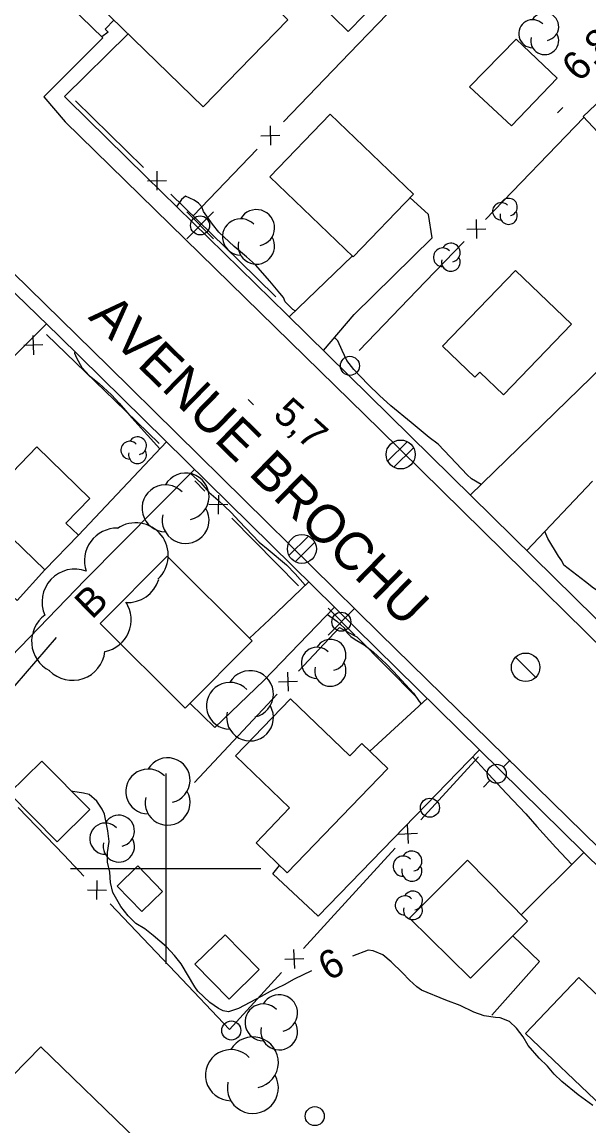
# Model space of a CAD drawing. Extents: x 381879 to 384696, y 5564785 to 5567594.
# Drawn here: x 382984.9 to 383044.4, y 5565173 to 5565288.9 of the extents above; entities that cross this region are included whole.
import ezdxf

# ---------------------------------------------------------------- set-up
doc = ezdxf.new("R2010")
doc.units = 0
for name, color, linetype in [('Niveau 19', 7, 'Continuous'), ('Niveau 2', 7, 'Continuous'), ('Niveau 21', 7, 'Continuous'), ('Niveau 22', 7, 'Continuous'), ('Niveau 3', 7, 'Continuous'), ('Niveau 31', 7, 'Continuous'), ('Niveau 36', 7, 'Continuous'), ('Niveau 37', 7, 'Continuous'), ('Niveau 44', 7, 'Continuous'), ('Niveau 52', 7, 'Continuous'), ('Niveau 61', 7, 'Continuous')]:
    doc.layers.add(name, color=color, linetype=linetype)

msp = doc.modelspace()

# ---------------------------------------------------------------- linework, layer by layer
at = {"layer": 'Niveau 19'}
for points in [[(383016.56, 5565254.4), (383019.78, 5565258.2), (383027.98, 5565266.25), (383027.6, 5565268.71), (383025.64, 5565270.47)], [(383019.61, 5565264.34), (383012.96, 5565257.94)], [(382977.69, 5565252.36), (382980.28, 5565250.02), (382987.48, 5565257.22)], [(383051.28, 5565248.2), (383045.95, 5565252.85), (383031.98, 5565239.23)], [(383000.09, 5565244.82), (382990.83, 5565235.01)], [(382987.32, 5565231.38), (382984.4, 5565228.17), (382978.03, 5565233.92), (382972.73, 5565228.26), (382967.87, 5565228.52), (382970.4, 5565224.82), (382975.08, 5565224.12), (382980.11, 5565223.76), (382983.75, 5565222.23), (382991.54, 5565230.32), (383003.03, 5565241.92)], [(383037.9, 5565233.41), (383044.81, 5565240.7)], [(383008.8, 5565224.2), (383010.89, 5565226.15), (383015.03, 5565230.11)], [(383017.72, 5565227.46), (383010.31, 5565219.74), (383005.16, 5565214.81), (383002.56, 5565217.35)], [(383021.42, 5565212.33), (383027.45, 5565217.88)], [(383032.94, 5565212.49), (383016.01, 5565195.01), (383011.25, 5565199.45), (383011.95, 5565200.34)], [(383043.9, 5565201.7), (383037.34, 5565195.17)], [(383036.43, 5565192.93), (383039.26, 5565190.26), (383034.24, 5565184.6)]]:
    msp.add_lwpolyline(points, dxfattribs=at)
at = {"layer": 'Niveau 2'}
for points in [[(383013.6, 5565258.56), (383013.34, 5565258.72), (383012.56, 5565259.52), (383012.38, 5565259.99), (383011.99, 5565260.43), (383010.95, 5565261.7), (383009.42, 5565263.41), (383008.48, 5565264.26), (383007.2, 5565265.35), (383005.58, 5565266.85), (383004.91, 5565267.68), (383003.96, 5565269.02), (383003.78, 5565269.51), (383003.45, 5565269.89), (383002.98, 5565270.21), (383002.07, 5565270.63), (383001.67, 5565270.27), (383001.37, 5565269.86), (383001.14, 5565269.53)], [(383033.13, 5565240.35), (383032.09, 5565240.94), (383031.64, 5565241.37), (383030.49, 5565242.57), (383028.59, 5565244.57), (383027.65, 5565245.29), (383025.76, 5565246.85), (383023.62, 5565248.6), (383022.43, 5565249.68), (383021.25, 5565250.85), (383019.74, 5565252.43), (383019.02, 5565253.36), (383018.53, 5565254.42), (383018.06, 5565255.41), (383017.73, 5565255.79)], [(382990.46, 5565254.3), (382990.44, 5565254.14), (382990.62, 5565253.65), (382991.2, 5565252.61), (382992, 5565251.74), (382993.01, 5565250.96), (382994.32, 5565249.76), (382995.1, 5565248.89), (382996.44, 5565247.33), (382998.1, 5565245.53), (382999.38, 5565244.07)], [(383002.62, 5565241.51), (383003.69, 5565240.5), (383004.52, 5565239.55), (383005.5, 5565238.69), (383006.87, 5565237.39), (383007.7, 5565236.49), (383009.82, 5565234.3), (383010.75, 5565233.51), (383012.68, 5565231.89), (383013.59, 5565230.97), (383014.66, 5565229.76)], [(383057.47, 5565222.55), (383056.98, 5565222.9), (383056.22, 5565223.69), (383055, 5565224.89), (383054.13, 5565225.49), (383053.25, 5565226.01), (383052.35, 5565226.69), (383051.33, 5565227.06), (383050.29, 5565227.3), (383047.99, 5565227.92), (383046.92, 5565228.33), (383045.92, 5565228.82), (383044.92, 5565229.45), (383044.08, 5565230.11), (383041.79, 5565231.86), (383041.58, 5565232.32), (383041.24, 5565232.81), (383040.11, 5565234.66), (383039.79, 5565235.41)], [(383016.99, 5565226.69), (383017.98, 5565225.99)], [(383017.98, 5565225.99), (383018.73, 5565225.27), (383019.05, 5565224.77), (383019.43, 5565224.38), (383019.9, 5565224.06), (383020.85, 5565223.51), (383021.78, 5565222.76), (383023.15, 5565221.52), (383023.91, 5565220.7), (383026, 5565218.43), (383026.6, 5565217.56), (383026.81, 5565217.29)], [(383032.21, 5565211.74), (383032.75, 5565211.17), (383033.89, 5565209.91), (383035.78, 5565207.89), (383037.8, 5565205.76), (383038.98, 5565204.43), (383040.96, 5565202.22), (383042.64, 5565200.44)], [(383015.31, 5565189.28), (383013.49, 5565188.38), (383012.45, 5565187.8), (383010.97, 5565187.1), (383010.04, 5565186.57), (383007.66, 5565185.31), (383006.58, 5565184.96), (383006.02, 5565185.05), (383005.55, 5565185.3), (383004.63, 5565185.95), (383003.36, 5565187.13), (383003.07, 5565187.6), (383001.62, 5565190), (383000.92, 5565190.88), (383000.07, 5565191.78), (382998.7, 5565192.99), (382997.82, 5565193.66), (382996.85, 5565194.25), (382996.06, 5565195.05), (382995.3, 5565196.01), (382994.45, 5565197.49), (382994.2, 5565198.54), (382994.14, 5565199.62), (382993.9, 5565200.69), (382993.89, 5565201.71), (382994.05, 5565202.84), (382993.91, 5565203.97), (382993.57, 5565205.73), (382993.32, 5565206.23), (382992.78, 5565207.1), (382991.95, 5565207.79), (382991.38, 5565207.93), (382990.26, 5565208.11), (382990.1, 5565208.14)], [(383044.84, 5565175.13), (383043.29, 5565176.24), (383041.58, 5565177.63), (383040.78, 5565178.42), (383040.07, 5565179.26), (383039.21, 5565180.09), (383038.05, 5565181.42), (383037.52, 5565182.32), (383036.84, 5565183.23), (383036.08, 5565183.93), (383035.12, 5565184.34), (383034.61, 5565184.35), (383033.44, 5565184.54), (383032.36, 5565184.94), (383030.92, 5565185.61), (383029.41, 5565186.18), (383026.86, 5565187.25), (383026.37, 5565187.6), (383025.59, 5565188.27), (383024.86, 5565189.05), (383023.67, 5565190.22), (383022.8, 5565190.94), (383021.77, 5565191.38), (383021.24, 5565191.42), (383019.61, 5565190.82)]]:
    msp.add_lwpolyline(points, dxfattribs=at)
at = {"layer": 'Niveau 21'}
msp.add_lwpolyline([(382987.2, 5565281.06), (382989.44, 5565278.42), (383022.49, 5565246.1), (383059.26, 5565209.91), (383088.37, 5565181.5), (383101.7, 5565168.8)], dxfattribs=at)
at = {"layer": 'Niveau 22'}
for points in [[(382994.58, 5565289.12), (382993.64, 5565288.16), (382993.96, 5565287.85), (382993.31, 5565287.34)], [(382989.72, 5565280.74), (382989.39, 5565281.09), (382996.07, 5565287.68)], [(382989.72, 5565280.74), (382997.91, 5565272.69), (383012.71, 5565258.19), (383105.48, 5565166.92), (383105.5, 5565166.9)], [(382963, 5565271.7), (382966.05, 5565274.15), (382968.58, 5565274.75), (382971.52, 5565274.09), (382973.8, 5565272.5), (382994.02, 5565252.72), (383022.46, 5565224.72), (383053.73, 5565194.11), (383080.99, 5565167.59), (383084.55, 5565163.99)], [(383092.98, 5565153.68), (383056.83, 5565188.98), (383017.75, 5565227.43), (382988.78, 5565255.96), (382969.58, 5565274.53)]]:
    msp.add_lwpolyline(points, dxfattribs=at)
at = {"layer": 'Niveau 3'}
for p, q in [((383041.12, 5565279.36), (383041.69, 5565279.93)), ((383008.66, 5565249.26), (383009.23, 5565248.69))]:
    msp.add_line(p, q, dxfattribs=at)
at = {"layer": 'Niveau 31'}
for points in [[(383003.94, 5565280.01), (382986.87, 5565296.63), (382988.63, 5565298.43), (382984.43, 5565302.53), (382982.52, 5565300.57), (382962.24, 5565320.32), (382969.15, 5565327.42), (382972.16, 5565324.49), (382979.7, 5565332.23), (382986.68, 5565325.44), (382979.09, 5565317.64), (382989.54, 5565307.45), (382987.76, 5565305.63), (382988.83, 5565304.59), (382987.51, 5565303.24), (382990.5, 5565300.32), (382995.79, 5565305.75), (383012.84, 5565289.15)], [(383015.99, 5565290.99), (383019.45, 5565294.53), (383022.6, 5565291.46), (383019.14, 5565287.92)], [(383036.3, 5565278), (383041.1, 5565283), (383036.8, 5565287.1), (383031.9, 5565282.1)], [(383043.82, 5565278.99), (383046.43, 5565281.44), (383048.96, 5565278.74), (383046.35, 5565276.29)], [(383017.25, 5565279.22), (383026, 5565270.84), (383019.69, 5565264.26), (383010.94, 5565272.64)], [(383042.6, 5565257.19), (383035.45, 5565249.76), (383032.97, 5565252.15), (383032.45, 5565251.61), (383029.06, 5565254.87), (383036.73, 5565262.83)], [(382987.32, 5565231.38), (382980.42, 5565238.03), (382986.46, 5565244.28), (382992.05, 5565238.88), (382989.53, 5565236.27), (382990.83, 5565235.01)], [(383000.14, 5565232.81), (383009.09, 5565223.92), (383002.06, 5565216.85), (382993.11, 5565225.74)], [(383023.31, 5565210.51), (383012.76, 5565199.56), (383009.49, 5565202.72), (383013, 5565206.37), (383007.33, 5565211.83), (383013.11, 5565217.83), (383019.33, 5565211.84), (383020.59, 5565213.13)], [(382986.99, 5565211.3), (382992.02, 5565206.2), (382988.59, 5565202.81), (382983.56, 5565207.91)], [(382997.06, 5565200.28), (382999.66, 5565197.61), (382997.5, 5565195.5), (382994.9, 5565198.17)], [(383032, 5565188.5), (383038, 5565194.5), (383031.7, 5565200.9), (383025.6, 5565194.8)], [(383006.23, 5565193.06), (383009.82, 5565189.39), (383006.65, 5565186.29), (383003.06, 5565189.96)], [(383043.37, 5565188.55), (383051.38, 5565180.93), (383045.79, 5565175.06), (383037.78, 5565182.68)], [(382986.9, 5565181.3), (382980.9, 5565175.2), (382991, 5565165.3), (382997, 5565171.5)]]:
    msp.add_lwpolyline(points, close=True, dxfattribs=at)
at = {"layer": 'Niveau 36'}
for p, q in [((383005.03, 5565268.96), (383002.21, 5565266.14)), ((383005.03, 5565266.14), (383002.21, 5565268.96)), ((383025.36, 5565244.83), (383023.3, 5565242.79)), ((383023.96, 5565242.15), (383026.02, 5565244.19)), ((383014.99, 5565234.91), (383012.93, 5565232.87)), ((383013.59, 5565232.23), (383015.65, 5565234.27)), ((383019.86, 5565227.34), (383017.04, 5565224.52)), ((383019.86, 5565224.52), (383017.04, 5565227.34)), ((383038.86, 5565220.08), (383036.74, 5565222.2)), ((383036.17, 5565211.38), (383035.46, 5565210.68)), ((383033.35, 5565208.55), (383034.04, 5565209.27))]:
    msp.add_line(p, q, dxfattribs=at)
for centre, radius in [((383003.61, 5565267.55), 1), ((383019.34, 5565252.8), 1), ((383024.67, 5565243.49), 1.52), ((383014.3, 5565233.57), 1.52), ((383018.44, 5565225.93), 1), ((383037.79, 5565221.14), 1.5), ((383034.75, 5565209.96), 1), ((383027.74, 5565206.4), 1), ((383006.89, 5565183), 1), ((383015.65, 5565174.01), 1)]:
    msp.add_circle(centre, radius, dxfattribs=at)
at = {"layer": 'Niveau 37'}
for p, q in [((383010.97, 5565277.99), (383011.01, 5565275.99)), ((383009.99, 5565276.97), (383011.99, 5565277.01)), ((382999.11, 5565271.24), (382999.09, 5565273.24)), ((382998.1, 5565272.23), (383000.1, 5565272.25)), ((383031.61, 5565267.14), (383033.61, 5565267.18)), ((383032.59, 5565268.16), (383032.63, 5565266.16)), ((382986.14, 5565253.96), (382986.07, 5565255.97)), ((382987.1, 5565255), (382985.1, 5565254.93)), ((383005.53, 5565239.23), (383005.52, 5565237.22)), ((383006.53, 5565238.22), (383004.52, 5565238.23)), ((383013.85, 5565219.65), (383011.84, 5565219.58)), ((383012.88, 5565218.62), (383012.81, 5565220.62)), ((383025.48, 5565202.63), (383025.39, 5565204.63)), ((383026.44, 5565203.68), (383024.44, 5565203.59)), ((382992.77, 5565196.75), (382992.82, 5565198.75)), ((382991.79, 5565197.78), (382993.79, 5565197.73)), ((383014.52, 5565190.54), (383012.52, 5565190.45)), ((383013.57, 5565189.5), (383013.47, 5565191.5))]:
    msp.add_line(p, q, dxfattribs=at)
for points in [[(383026.24, 5565292.84), (383019.31, 5565285.63)], [(383019.31, 5565285.63), (383012.38, 5565278.43)], [(382990.52, 5565280.63), (382997.67, 5565273.64)], [(383043.91, 5565278.89), (383033.57, 5565268.17)], [(383009.6, 5565275.54), (383002.87, 5565268.55)], [(383000.53, 5565270.84), (383007.68, 5565263.85)], [(383031.35, 5565265.86), (383027.25, 5565261.61)], [(383007.68, 5565263.85), (383011.58, 5565260.03)], [(383027.25, 5565261.61), (383020.31, 5565254.42)], [(382987.48, 5565256.1), (382994.66, 5565249.15)], [(382994.66, 5565249.15), (382999.33, 5565244.63)], [(383004.12, 5565239.65), (383003.05, 5565240.73)], [(383013.96, 5565229.69), (383006.93, 5565236.8)], [(382988.51, 5565224.26), (382981.97, 5565216.7)], [(383013.96, 5565220.73), (383018.24, 5565225.31), (383019.78, 5565224.49)], [(383019.78, 5565224.49), (383020.06, 5565224.34), (383026.31, 5565218.05)], [(383003.04, 5565209.05), (383011.71, 5565218.33)], [(383026.78, 5565205.11), (383032.84, 5565211.75)], [(382984.5, 5565206.42), (382989.33, 5565201.4), (382991.41, 5565199.2)], [(383017.35, 5565194.77), (383024.09, 5565202.16)], [(382994.17, 5565196.3), (383001.05, 5565189.05)], [(383014.46, 5565191.6), (383017.35, 5565194.77)], [(383001.05, 5565189.05), (383006.7, 5565183.1), (383012.15, 5565189.09)]]:
    msp.add_lwpolyline(points, dxfattribs=at)
at = {"layer": 'Niveau 44'}
for centre, radius, start, end in [((383038.53, 5565287.68), 1.47, 44.1153, 269.8039), ((383039.79, 5565288.42), 1.47, 282.2692, 149.7262), ((383039.79, 5565286.95), 1.47, 166.9368, 29.6212), ((383035.23, 5565269.03), 0.909, 44.1153, 269.8039), ((383036.01, 5565269.48), 0.909, 282.2692, 149.7262), ((383007.87, 5565266.34), 1.91, 44.1153, 269.8039), ((383009.52, 5565267.3), 1.91, 282.2692, 149.7262), ((383036.01, 5565268.57), 0.909, 166.9368, 29.6212), ((383009.52, 5565265.38), 1.91, 166.9368, 29.6212), ((383029.09, 5565264.2), 0.982, 44.1153, 269.8039), ((383029.94, 5565264.69), 0.982, 282.2692, 149.7262), ((383029.94, 5565263.71), 0.982, 166.9368, 29.6212), ((382997.04, 5565244.41), 0.935, 282.2692, 149.7262), ((382996.23, 5565243.94), 0.935, 44.1153, 269.8039), ((382997.04, 5565243.47), 0.935, 166.9368, 29.6212), ((383002.09, 5565239.08), 2.46, 282.2692, 149.7262), ((382999.97, 5565237.84), 2.46, 44.1153, 269.8039), ((383002.09, 5565236.61), 2.46, 166.9368, 29.6212), ((382996.85, 5565232.9), 3.42, 312.9765, 124.0605), ((383015.88, 5565221.61), 1.64, 44.1153, 269.8039), ((383017.29, 5565222.43), 1.64, 282.2692, 149.7262), ((383008.85, 5565218.33), 2.46, 282.2692, 149.7262), ((383017.29, 5565220.79), 1.64, 166.9368, 29.6212), ((383006.74, 5565217.1), 2.46, 44.1153, 269.8039), ((383008.85, 5565215.87), 2.46, 166.9368, 29.6212), ((383000.2, 5565209.28), 2.36, 282.2692, 149.7262), ((382998.17, 5565208.1), 2.36, 44.1153, 269.8039), ((383000.2, 5565206.92), 2.36, 166.9368, 29.6212), ((382995.08, 5565203.97), 1.64, 282.2692, 149.7262), ((382993.67, 5565203.15), 1.64, 44.1153, 269.8039), ((382995.08, 5565202.33), 1.64, 166.9368, 29.6212), ((383024.93, 5565200.26), 1.06, 44.1153, 269.8039), ((383025.84, 5565200.79), 1.06, 282.2692, 149.7262), ((383025.84, 5565199.74), 1.06, 166.9368, 29.6212), ((383025.96, 5565196.64), 1, 282.2692, 149.7262), ((383025.1, 5565196.14), 1, 44.1153, 269.8039), ((383025.96, 5565195.64), 1, 166.9368, 29.6212), ((383011.91, 5565184.83), 1.93, 282.2692, 149.7262), ((383010.25, 5565183.86), 1.93, 44.1153, 269.8039), ((383011.91, 5565182.89), 1.93, 166.9368, 29.6212), ((383009.15, 5565179.65), 2.68, 282.2692, 149.7262), ((383006.85, 5565178.31), 2.68, 44.1153, 269.8039), ((383009.15, 5565176.97), 2.68, 166.9368, 29.6212)]:
    msp.add_arc(centre, radius, start, end, dxfattribs=at)
for centre, major_axis, ratio, start_param, end_param in [((382994.9, 5565232.33), (-2.31, -2.54), 0.99875, 3.869087, 5.776504), ((382990.44, 5565228.03), (-2.53, -2.31), 0.998757, 3.609583, 5.97114), ((382995.99, 5565231.37), (2.1, 2.71), 0.998755, 3.738569, 5.071259), ((382992.95, 5565226.16), (2.29, -2.56), 0.993462, 5.748989, 7.688274), ((382989.35, 5565223.86), (0.12, -3.43), 0.999617, 3.743059, 5.777324), ((382990.22, 5565223.2), (3.32, 0.86), 0.998754, 3.667743, 5.913201)]:
    msp.add_ellipse(centre, major_axis=major_axis, ratio=ratio, start_param=start_param, end_param=end_param, dxfattribs=at)
at = {"layer": 'Niveau 52'}
msp.add_lwpolyline([(382968.07, 5565299.93), (382973.98, 5565306.07), (382993.39, 5565287.26), (382987.2, 5565281.06)], dxfattribs=at)
at = {"layer": 'Niveau 61'}
for points in [[(383000, 5565210), (383000, 5565200), (383000, 5565190)], [(382990, 5565200), (383000, 5565200), (383010, 5565200)]]:
    msp.add_lwpolyline(points, dxfattribs=at)

# ---------------------------------------------------------------- texts
at = {"layer": 'Niveau 2'}
msp.add_text('6', height=3, rotation=29.0183, dxfattribs=at).set_placement((383017.1, 5565188.14))
at = {"layer": 'Niveau 21'}
msp.add_text('AVENUE BROCHU', height=4, rotation=315.6892, dxfattribs=at).set_placement((382991.79, 5565257.83))
at = {"layer": 'Niveau 3'}
for s, rotation, p in [('6,8', 44.7717, (383043.41, 5565282.49)), ('5,7  ', 317.9168, (383011.14, 5565247.5))]:
    msp.add_text(s, height=3, rotation=rotation, dxfattribs=at).set_placement(p)
at = {"layer": 'Niveau 44'}
msp.add_text('B', height=3, rotation=44.7707, dxfattribs=at).set_placement((382992.26, 5565226.09))

doc.saveas('drawing.dxf')
